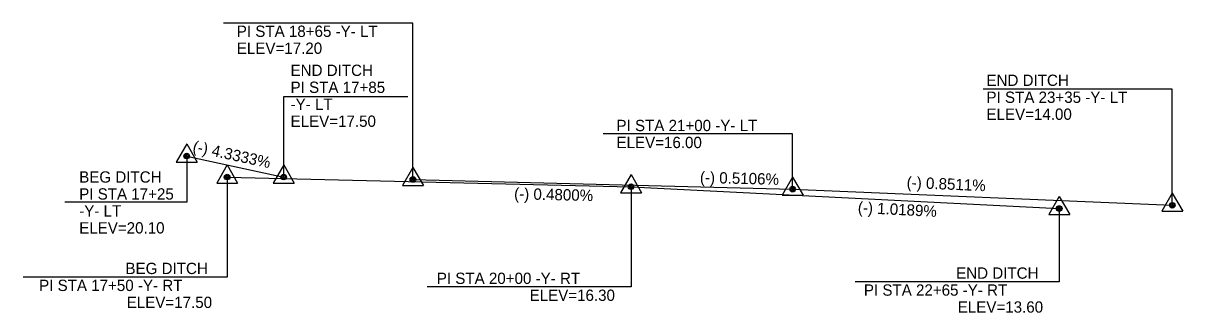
# Model space of a CAD drawing. Extents: x 2179808 to 2190174, y 63168 to 78602.
# Drawn here: x 2180565 to 2181282, y 75161 to 75340 of the extents above; entities that cross this region are included whole.
import ezdxf

# ---------------------------------------------------------------- set-up
doc = ezdxf.new("R2010")
doc.units = 0
for name, color, linetype in [('Default', 7, 'Continuous'), ('Prop Vertical Profile Ditch Grade Left', 7, 'Continuous'), ('Prop Vertical Profile Ditch Grade Left Label', 7, 'Continuous'), ('Prop Vertical Profile Ditch Grade Right', 7, 'Continuous'), ('Prop Vertical Profile Ditch Grade Right Label', 7, 'Continuous'), ('Prop VPI Ditch Grade Left Label', 7, 'Continuous'), ('Prop VPI Ditch Grade Right Label', 7, 'Continuous')]:
    doc.layers.add(name, color=color, linetype=linetype)

msp = doc.modelspace()

# ---------------------------------------------------------------- linework, layer by layer
at = {"layer": 'Default'}
for p, q in [((2180665.9, 75265.26), (2180659.45, 75254.06)), ((2180665.9, 75265.26), (2180672.4, 75254.06)), ((2180659.45, 75254.06), (2180672.4, 75254.06)), ((2180690.9, 75252.26), (2180684.45, 75241.06)), ((2180690.9, 75252.26), (2180697.4, 75241.06)), ((2180725.9, 75252.26), (2180719.45, 75241.06)), ((2180725.9, 75252.26), (2180732.4, 75241.06)), ((2180805.9, 75250.76), (2180799.45, 75239.56)), ((2180805.9, 75250.76), (2180812.4, 75239.56)), ((2180940.9, 75246.26), (2180934.45, 75235.06)), ((2180940.9, 75246.26), (2180947.4, 75235.06)), ((2181040.9, 75244.76), (2181034.45, 75233.56)), ((2181040.9, 75244.76), (2181047.4, 75233.56)), ((2180684.45, 75241.06), (2180697.4, 75241.06)), ((2180719.45, 75241.06), (2180732.4, 75241.06)), ((2180799.45, 75239.56), (2180812.4, 75239.56)), ((2180934.45, 75235.06), (2180947.4, 75235.06)), ((2181034.45, 75233.56), (2181047.4, 75233.56)), ((2181205.9, 75232.76), (2181199.45, 75221.56)), ((2181205.9, 75232.76), (2181212.4, 75221.56)), ((2181275.9, 75234.76), (2181269.45, 75223.56)), ((2181275.9, 75234.76), (2181282.4, 75223.56)), ((2181269.45, 75223.56), (2181282.4, 75223.56)), ((2181199.45, 75221.56), (2181212.4, 75221.56))]:
    msp.add_line(p, q, dxfattribs=at)
for centre, radius in [((2180665.9, 75257.78), 1.75), ((2180665.9, 75257.78), 1.2), ((2180690.9, 75244.78), 1.75), ((2180690.9, 75244.78), 1.2), ((2180725.9, 75244.78), 1.75), ((2180725.9, 75244.78), 1.2), ((2180805.9, 75243.28), 1.75), ((2180805.9, 75243.28), 1.2), ((2180940.9, 75238.78), 1.75), ((2180940.9, 75238.78), 1.2), ((2181040.9, 75237.28), 1.75), ((2181040.9, 75237.28), 1.2), ((2181205.9, 75225.28), 1.75), ((2181205.9, 75225.28), 1.2), ((2181275.9, 75227.28), 1.75), ((2181275.9, 75227.28), 1.2)]:
    msp.add_circle(centre, radius, dxfattribs=at)
at = {"layer": 'Prop Vertical Profile Ditch Grade Left'}
msp.add_line((2180665.9, 75257.78), (2180725.9, 75244.78), dxfattribs=at)
msp.add_lwpolyline([(2180805.9, 75243.28), (2181040.9, 75237.28), (2181275.9, 75227.28)], dxfattribs=at)
at = {"layer": 'Prop Vertical Profile Ditch Grade Right'}
msp.add_lwpolyline([(2180690.9, 75244.78), (2180940.9, 75238.78), (2181205.9, 75225.28)], dxfattribs=at)
at = {"layer": 'Prop VPI Ditch Grade Left Label'}
for points in [[(2180805.9, 75243.28), (2180805.9, 75340.02), (2180688.74, 75340.02)], [(2181275.9, 75227.28), (2181275.9, 75299.17), (2181158.74, 75299.17)], [(2180725.9, 75244.78), (2180725.9, 75294.71), (2180802.7, 75294.71)], [(2181040.9, 75237.28), (2181040.9, 75271.47), (2180923.74, 75271.47)], [(2180665.9, 75257.78), (2180665.9, 75229.16), (2180590.44, 75229.16)]]:
    msp.add_lwpolyline(points, dxfattribs=at)
for centre in [(2180665.9, 75257.78), (2180725.9, 75244.78), (2180805.9, 75243.28), (2181040.9, 75237.28), (2181275.9, 75227.28)]:
    msp.add_circle(centre, 0.5, dxfattribs=at)
at = {"layer": 'Prop VPI Ditch Grade Right Label'}
for points in [[(2180690.9, 75244.78), (2180690.9, 75182.69), (2180564.69, 75182.69)], [(2180940.9, 75238.78), (2180940.9, 75176.69), (2180814.69, 75176.69)], [(2181205.9, 75225.28), (2181205.9, 75179.8), (2181079.69, 75179.8)]]:
    msp.add_lwpolyline(points, dxfattribs=at)
for centre in [(2180690.9, 75244.78), (2180940.9, 75238.78), (2181205.9, 75225.28)]:
    msp.add_circle(centre, 0.5, dxfattribs=at)

# ---------------------------------------------------------------- texts
at = {"layer": 'Prop Vertical Profile Ditch Grade Left Label'}
for s, rotation, p in [('(-) 4.3333%', 347.77488, (2180669.16, 75260.52)), ('(-) 0.5106%', 358.53745, (2180983.47, 75241.14)), ('(-) 0.8511%', 357.56335, (2181111.38, 75238.04))]:
    msp.add_text(s, height=7, rotation=rotation, dxfattribs=at).set_placement(p)
at = {"layer": 'Prop Vertical Profile Ditch Grade Right Label'}
for s, rotation, p in [('(-) 0.4800%', 358.62517, (2180868.47, 75231.03)), ('(-) 1.0189%', 357.08368, (2181081.14, 75222.53))]:
    msp.add_text(s, height=7, rotation=rotation, dxfattribs=at).set_placement(p)
at = {"layer": 'Prop VPI Ditch Grade Left Label'}
for s, p in [('PI STA 18+65 -Y- LT', (2180696.9, 75331.52)), ('ELEV=17.20', (2180696.9, 75321.02)), ('END DITCH', (2180730.18, 75307.34)), ('PI STA 17+85', (2180730.18, 75296.84)), ('END DITCH', (2181160.88, 75301.17)), ('PI STA 23+35 -Y- LT', (2181160.88, 75290.67)), ('-Y- LT', (2180730.18, 75286.34)), ('ELEV=17.50', (2180730.18, 75275.84)), ('ELEV=14.00', (2181160.88, 75280.17)), ('PI STA 21+00 -Y- LT', (2180931.9, 75273.18)), ('ELEV=16.00', (2180931.9, 75262.68)), ('BEG DITCH', (2180599.35, 75241.3)), ('PI STA 17+25', (2180599.35, 75230.8)), ('-Y- LT', (2180599.35, 75220.3)), ('ELEV=20.10', (2180599.35, 75209.8))]:
    msp.add_text(s, height=7, dxfattribs=at).set_placement(p)
at = {"layer": 'Prop VPI Ditch Grade Right Label'}
for s, p in [('BEG DITCH', (2180627.99, 75184.69)), ('PI STA 17+50 -Y- RT', (2180574.54, 75174.19)), ('ELEV=17.50', (2180628.77, 75163.69))]:
    msp.add_text(s, height=7, dxfattribs=at).set_placement(p)
for s, p in [('END DITCH', (2181142.11, 75181.8)), ('PI STA 20+00 -Y- RT', (2180820.68, 75178.57)), ('ELEV=16.30', (2180878.11, 75168.07)), ('PI STA 22+65 -Y- RT', (2181085.02, 75171.3)), ('ELEV=13.60', (2181143.11, 75160.8))]:
    msp.add_text(s, height=7, rotation=360, dxfattribs=at).set_placement(p)

doc.saveas('drawing.dxf')
